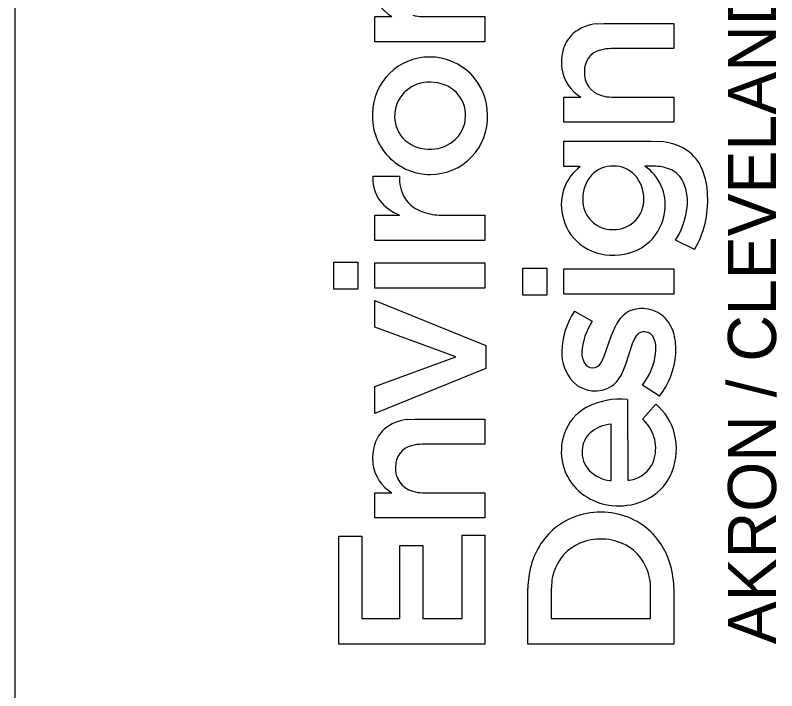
# Model space of a CAD drawing. Extents: x -0.3 to 34, y 0 to 22.
# Drawn here: x 32 to 32.901, y 2.583 to 3.382 of the extents above; entities that cross this region are included whole.
import ezdxf

# ---------------------------------------------------------------- set-up
doc = ezdxf.new("R2010")
doc.units = 0
doc.layers.add('SH_Border', color=7, linetype='Continuous')
doc.layers.add('SH_Data', color=7, linetype='Continuous')

msp = doc.modelspace()

# ---------------------------------------------------------------- linework, layer by layer
at = {"layer": 'SH_Border'}
msp.add_line((32, 0.5), (32, 21.5), dxfattribs=at)
at = {"layer": 'SH_Data'}
for p, q in [((32.42542, 3.38066), (32.44552, 3.38071)), ((32.42542, 3.35086), (32.42542, 3.38066)), ((32.48222, 3.38071), (32.55569, 3.38071)), ((32.55569, 3.38071), (32.55571, 3.35096)), ((32.68784, 3.3722), (32.69634, 3.37266)), ((32.69634, 3.37266), (32.77916, 3.37266)), ((32.77916, 3.37266), (32.77917, 3.34287)), ((32.55571, 3.35096), (32.42542, 3.35086)), ((32.77917, 3.34287), (32.70485, 3.3428)), ((32.64888, 3.2855), (32.66897, 3.28555)), ((32.64888, 3.25569), (32.64888, 3.2855)), ((32.70568, 3.28555), (32.77915, 3.28555)), ((32.77915, 3.28555), (32.77917, 3.25579)), ((32.77917, 3.25579), (32.64888, 3.25569)), ((32.6489, 3.20336), (32.64889, 3.23322)), ((32.64889, 3.23322), (32.75236, 3.23322)), ((32.75236, 3.23322), (32.76191, 3.23285)), ((32.66836, 3.20336), (32.6489, 3.20336)), ((32.75763, 3.20356), (32.74487, 3.20361)), ((32.42299, 3.19193), (32.45454, 3.19193)), ((32.42542, 3.14577), (32.45473, 3.14579)), ((32.42542, 3.11593), (32.42542, 3.14577)), ((32.50413, 3.14581), (32.55571, 3.14573)), ((32.55571, 3.14573), (32.55565, 3.11593)), ((32.55565, 3.11593), (32.42542, 3.11593)), ((32.8036, 3.10491), (32.7812, 3.11598)), ((32.37705, 3.05818), (32.37705, 3.09026)), ((32.37705, 3.09026), (32.40543, 3.09026)), ((32.40543, 3.09026), (32.40543, 3.05818)), ((32.42542, 3.05942), (32.42542, 3.08928)), ((32.42542, 3.08928), (32.55571, 3.08928)), ((32.55571, 3.08928), (32.55571, 3.05942)), ((32.60051, 3.05111), (32.60051, 3.08319)), ((32.60051, 3.08319), (32.62889, 3.08319)), ((32.62889, 3.08319), (32.62889, 3.05111)), ((32.64888, 3.05234), (32.64888, 3.0822)), ((32.64888, 3.0822), (32.77917, 3.0822)), ((32.77917, 3.0822), (32.77917, 3.05234)), ((32.40543, 3.05818), (32.37705, 3.05818)), ((32.55571, 3.05942), (32.42542, 3.05942)), ((32.62889, 3.05111), (32.60051, 3.05111)), ((32.77917, 3.05234), (32.64888, 3.05234)), ((32.42542, 3.01327), (32.42542, 3.0446)), ((32.42542, 3.0446), (32.5567, 2.9913)), ((32.66151, 3.03207), (32.68268, 3.02025)), ((32.52117, 2.97798), (32.42542, 3.01327)), ((32.70483, 3.00258), (32.71036, 3.01526)), ((32.69675, 2.97868), (32.70483, 3.00258)), ((32.73342, 3.00101), (32.72985, 2.9933)), ((32.5567, 2.9913), (32.5567, 2.96441)), ((32.72985, 2.9933), (32.72213, 2.96882)), ((32.42542, 2.94294), (32.52117, 2.97798)), ((32.69299, 2.97117), (32.69675, 2.97868)), ((32.5567, 2.96441), (32.42542, 2.91086)), ((32.72213, 2.96882), (32.71822, 2.95921)), ((32.42542, 2.91086), (32.42542, 2.94294)), ((32.76214, 2.93141), (32.74198, 2.94469)), ((32.72453, 2.92747), (32.72463, 2.83195)), ((32.74228, 2.90465), (32.75768, 2.922)), ((32.46439, 2.90397), (32.47289, 2.90443)), ((32.47289, 2.90443), (32.55571, 2.90443)), ((32.55571, 2.90443), (32.55571, 2.87465)), ((32.70489, 2.83182), (32.70489, 2.89834)), ((32.55571, 2.87465), (32.4814, 2.87457)), ((32.70361, 2.83165), (32.70489, 2.83182)), ((32.42542, 2.81728), (32.44552, 2.81733)), ((32.42542, 2.78747), (32.42542, 2.81728)), ((32.48222, 2.81733), (32.55569, 2.81733)), ((32.55569, 2.81733), (32.55571, 2.78756)), ((32.55571, 2.78756), (32.42542, 2.78747)), ((32.38298, 2.63791), (32.38298, 2.76598)), ((32.38298, 2.76598), (32.41012, 2.76598)), ((32.41012, 2.76598), (32.41012, 2.66827)), ((32.52857, 2.66827), (32.52857, 2.76722)), ((32.52857, 2.76722), (32.55571, 2.76722)), ((32.55571, 2.76722), (32.55571, 2.63791)), ((32.45503, 2.66827), (32.45503, 2.75488)), ((32.45503, 2.75488), (32.48218, 2.75488)), ((32.48218, 2.75488), (32.48218, 2.66827)), ((32.77847, 2.71497), (32.77917, 2.7021)), ((32.60643, 2.63799), (32.60644, 2.704)), ((32.63465, 2.71178), (32.63407, 2.7023)), ((32.63407, 2.7023), (32.63407, 2.66838)), ((32.75149, 2.66834), (32.75153, 2.70239)), ((32.77917, 2.7021), (32.77917, 2.638)), ((32.41012, 2.66827), (32.45503, 2.66827)), ((32.48218, 2.66827), (32.52857, 2.66827)), ((32.63407, 2.66838), (32.75149, 2.66834)), ((32.55571, 2.63791), (32.38298, 2.63791)), ((32.77917, 2.638), (32.60643, 2.63799))]:
    msp.add_line(p, q, dxfattribs=at)
for points in [[(32.42542, 3.35086), (32.42542, 3.38066), (32.44552, 3.38071)], [(32.48222, 3.38071), (32.55569, 3.38071), (32.55571, 3.35096), (32.42542, 3.35086)], [(32.68784, 3.3722), (32.69634, 3.37266), (32.77916, 3.37266), (32.77917, 3.34287), (32.70485, 3.3428)], [(32.64888, 3.25569), (32.64888, 3.2855), (32.66897, 3.28555)], [(32.70568, 3.28555), (32.77915, 3.28555), (32.77917, 3.25579), (32.64888, 3.25569)], [(32.66836, 3.20336), (32.6489, 3.20336), (32.64889, 3.23322), (32.75236, 3.23322), (32.76191, 3.23285)], [(32.75763, 3.20356), (32.74487, 3.20361)], [(32.42299, 3.19193), (32.45454, 3.19193)], [(32.50413, 3.14581), (32.55571, 3.14573), (32.55565, 3.11593), (32.42542, 3.11593)], [(32.42542, 3.11593), (32.42542, 3.14577), (32.45473, 3.14579)], [(32.8036, 3.10491), (32.7812, 3.11598)], [(32.66151, 3.03207), (32.68268, 3.02025)], [(32.69299, 2.97117), (32.69675, 2.97868), (32.70483, 3.00258), (32.71036, 3.01526)], [(32.73342, 3.00101), (32.72985, 2.9933), (32.72213, 2.96882), (32.71822, 2.95921)], [(32.76214, 2.93141), (32.74198, 2.94469)], [(32.72453, 2.92747), (32.72463, 2.83195)], [(32.74228, 2.90465), (32.75768, 2.922)], [(32.46439, 2.90397), (32.47289, 2.90443), (32.55571, 2.90443), (32.55571, 2.87465), (32.4814, 2.87457)], [(32.70361, 2.83165), (32.70489, 2.83182), (32.70489, 2.89834)], [(32.42542, 2.78747), (32.42542, 2.81728), (32.44552, 2.81733)], [(32.48222, 2.81733), (32.55569, 2.81733), (32.55571, 2.78756), (32.42542, 2.78747)], [(32.77847, 2.71497), (32.77917, 2.7021), (32.77917, 2.638), (32.60643, 2.63799)], [(32.60643, 2.63799), (32.60644, 2.704)], [(32.63465, 2.71178), (32.63407, 2.7023), (32.63407, 2.66838), (32.75149, 2.66834), (32.75153, 2.70239)]]:
    msp.add_lwpolyline(points, dxfattribs=at)
for points in [[(32.37705, 3.05818), (32.37705, 3.09026), (32.40543, 3.09026), (32.40543, 3.05818)], [(32.42542, 3.05942), (32.42542, 3.08928), (32.55571, 3.08928), (32.55571, 3.05942)], [(32.60051, 3.05111), (32.60051, 3.08319), (32.62889, 3.08319), (32.62889, 3.05111)], [(32.64888, 3.05234), (32.64888, 3.0822), (32.77917, 3.0822), (32.77917, 3.05234)], [(32.42542, 2.91086), (32.42542, 2.94294), (32.52117, 2.97798), (32.42542, 3.01327), (32.42542, 3.0446), (32.5567, 2.9913), (32.5567, 2.96441)], [(32.38298, 2.63791), (32.38298, 2.76598), (32.41012, 2.76598), (32.41012, 2.66827), (32.45503, 2.66827), (32.45503, 2.75488), (32.48218, 2.75488), (32.48218, 2.66827), (32.52857, 2.66827), (32.52857, 2.76722), (32.55571, 2.76722), (32.55571, 2.63791)]]:
    msp.add_lwpolyline(points, close=True, dxfattribs=at)
for centre, radius, start, end in [((32.47027, 3.42141), 0.04763, 188.96462, 238.69865), ((32.47027, 3.42141), 0.04763, 188.96462, 238.69865), ((32.48183, 3.42286), 0.04215, 254.08913, 270.52838), ((32.48183, 3.42286), 0.04215, 254.08913, 270.52838), ((32.69216, 3.32251), 0.04988, 94.97056, 130.22484), ((32.69216, 3.32251), 0.04988, 94.97056, 130.22484), ((32.68694, 3.33085), 0.04016, 132.22383, 161.68229), ((32.68694, 3.33085), 0.04016, 132.22383, 161.68229), ((32.70217, 3.32642), 0.05602, 162.27398, 187.79173), ((32.70217, 3.32642), 0.05602, 162.27398, 187.79173), ((32.70453, 3.29679), 0.04601, 89.60515, 105.33026), ((32.70453, 3.29679), 0.04601, 89.60515, 105.33026), ((32.69828, 3.31689), 0.02498, 103.68683, 182.21395), ((32.69828, 3.31689), 0.02498, 103.68683, 182.21395), ((32.49014, 3.26543), 0.0674, 89.84756, 179.64047), ((32.49014, 3.26543), 0.0674, 89.84756, 179.64047), ((32.49057, 3.26474), 0.0681, 359.54009, 90.21138), ((32.49057, 3.26474), 0.0681, 359.54009, 90.21138), ((32.69372, 3.32624), 0.04763, 188.96462, 238.69865), ((32.69372, 3.32624), 0.04763, 188.96462, 238.69865), ((32.7008, 3.31381), 0.02757, 175.58441, 255.13816), ((32.7008, 3.31381), 0.02757, 175.58441, 255.13816), ((32.48923, 3.26263), 0.0404, 87.04809, 175.57259), ((32.48923, 3.26263), 0.0404, 87.04809, 175.57259), ((32.49204, 3.25999), 0.04299, 45.84264, 90.98008), ((32.49204, 3.25999), 0.04299, 45.84264, 90.98008), ((32.49458, 3.26421), 0.03821, 357.88569, 44.15902), ((32.49458, 3.26421), 0.03821, 357.88569, 44.15902), ((32.70529, 3.32769), 0.04215, 254.08913, 270.52838), ((32.70529, 3.32769), 0.04215, 254.08913, 270.52838), ((32.49083, 3.26209), 0.06819, 176.8344, 270.40384), ((32.49083, 3.26209), 0.06819, 176.8344, 270.40384), ((32.48729, 3.2625), 0.03848, 175.15378, 221.14706), ((32.48729, 3.2625), 0.03848, 175.15378, 221.14706), ((32.49123, 3.26139), 0.06749, 270.06243, 2.37759), ((32.49123, 3.26139), 0.06749, 270.06243, 2.37759), ((32.49446, 3.26318), 0.0383, 308.28936, 359.43468), ((32.49446, 3.26318), 0.0383, 308.28936, 359.43468), ((32.48919, 3.26607), 0.04228, 223.09994, 268.80895), ((32.48919, 3.26607), 0.04228, 223.09994, 268.80895), ((32.49096, 3.2679), 0.04418, 266.56515, 308.06078), ((32.49096, 3.2679), 0.04418, 266.56515, 308.06078), ((32.75907, 3.16789), 0.06503, 53.40344, 87.49062), ((32.75907, 3.16789), 0.06503, 53.40344, 87.49062), ((32.76517, 3.18039), 0.05141, 21.60748, 50.5577), ((32.76517, 3.18039), 0.05141, 21.60748, 50.5577), ((32.70292, 3.15813), 0.05692, 127.37482, 192.22468), ((32.70292, 3.15813), 0.05692, 127.37482, 192.22468), ((32.70693, 3.16927), 0.0346, 88.47302, 136.42562), ((32.70693, 3.16927), 0.0346, 88.47302, 136.42562), ((32.70814, 3.16963), 0.03424, 44.27195, 90.47623), ((32.70814, 3.16963), 0.03424, 44.27195, 90.47623), ((32.71421, 3.15829), 0.05472, 352.1125, 55.92295), ((32.71421, 3.15829), 0.05472, 352.1125, 55.92295), ((32.75666, 3.15725), 0.04633, 65.01687, 88.8011), ((32.75666, 3.15725), 0.04633, 65.01687, 88.8011), ((32.7626, 3.17155), 0.03085, 26.26808, 63.80301), ((32.7626, 3.17155), 0.03085, 26.26808, 63.80301), ((32.73069, 3.16714), 0.08835, 1.15143, 21.3627), ((32.73069, 3.16714), 0.08835, 1.15143, 21.3627), ((32.46616, 3.18882), 0.04329, 175.87313, 216.34747), ((32.46616, 3.18882), 0.04329, 175.87313, 216.34747), ((32.50087, 3.18948), 0.04639, 176.9688, 209.60636), ((32.50087, 3.18948), 0.04639, 176.9688, 209.60636), ((32.71141, 3.16602), 0.0401, 137.46739, 182.33237), ((32.71141, 3.16602), 0.0401, 137.46739, 182.33237), ((32.70368, 3.166), 0.03996, 358.57141, 43.53765), ((32.70368, 3.166), 0.03996, 358.57141, 43.53765), ((32.73565, 3.16154), 0.05953, 349.30734, 23.43071), ((32.73565, 3.16154), 0.05953, 349.30734, 23.43071), ((32.47466, 3.19716), 0.05511, 218.09809, 248.7907), ((32.47466, 3.19716), 0.05511, 218.09809, 248.7907), ((32.49514, 3.18814), 0.04079, 211.94466, 253.2028), ((32.49514, 3.18814), 0.04079, 211.94466, 253.2028), ((32.70645, 3.1637), 0.03511, 178.88208, 271.08374), ((32.70645, 3.1637), 0.03511, 178.88208, 271.08374), ((32.70818, 3.16404), 0.03546, 268.27882, 1.55016), ((32.70818, 3.16404), 0.03546, 268.27882, 1.55016), ((32.70538, 3.16244), 0.11383, 329.6388, 3.25998), ((32.70538, 3.16244), 0.11383, 329.6388, 3.25998), ((32.50465, 3.2165), 0.07069, 252.46555, 269.57296), ((32.50465, 3.2165), 0.07069, 252.46555, 269.57296), ((32.70463, 3.15696), 0.05837, 190.75182, 231.28919), ((32.70463, 3.15696), 0.05837, 190.75182, 231.28919), ((32.70988, 3.15708), 0.05887, 313.74196, 353.8554), ((32.70988, 3.15708), 0.05887, 313.74196, 353.8554), ((32.70738, 3.16334), 0.08771, 327.31495, 351.57478), ((32.70738, 3.16334), 0.08771, 327.31495, 351.57478), ((32.70632, 3.16112), 0.06269, 232.46061, 272.59022), ((32.70632, 3.16112), 0.06269, 232.46061, 272.59022), ((32.70954, 3.15901), 0.06051, 269.6361, 312.70877), ((32.70954, 3.15901), 0.06051, 269.6361, 312.70877), ((32.73636, 2.98258), 0.08973, 146.53104, 178.7571), ((32.73636, 2.98258), 0.08973, 146.53104, 178.7571), ((32.74661, 2.99713), 0.04053, 125.51182, 153.41595), ((32.74661, 2.99713), 0.04053, 125.51182, 153.41595), ((32.7406, 3.0026), 0.03263, 80.17192, 122.51969), ((32.7406, 3.0026), 0.03263, 80.17192, 122.51969), ((32.74278, 2.99824), 0.03667, 47.79344, 84.68918), ((32.74278, 2.99824), 0.03667, 47.79344, 84.68918), ((32.74519, 2.9789), 0.07495, 146.51121, 176.91007), ((32.74519, 2.9789), 0.07495, 146.51121, 176.91007), ((32.73788, 2.9946), 0.04267, 14.9966, 46.20632), ((32.73788, 2.9946), 0.04267, 14.9966, 46.20632), ((32.74384, 2.99631), 0.01143, 76.66094, 155.7053), ((32.74384, 2.99631), 0.01143, 76.66094, 155.7053), ((32.74397, 2.99511), 0.01256, 21.5098, 78.52618), ((32.74397, 2.99511), 0.01256, 21.5098, 78.52618), ((32.71044, 2.98674), 0.07121, 355.83062, 15.39138), ((32.71044, 2.98674), 0.07121, 355.83062, 15.39138), ((32.72592, 2.98766), 0.03209, 354.57264, 22.06805), ((32.72592, 2.98766), 0.03209, 354.57264, 22.06805), ((32.69666, 2.98238), 0.05005, 177.53659, 222.79318), ((32.69666, 2.98238), 0.05005, 177.53659, 222.79318), ((32.6931, 2.98233), 0.02276, 178.47474, 211.08679), ((32.6931, 2.98233), 0.02276, 178.47474, 211.08679), ((32.68248, 2.99149), 0.0757, 321.81101, 354.79685), ((32.68248, 2.99149), 0.0757, 321.81101, 354.79685), ((32.68952, 2.9882), 0.09219, 321.9777, 355.87384), ((32.68952, 2.9882), 0.09219, 321.9777, 355.87384), ((32.68331, 2.9767), 0.01148, 212.23676, 268.37769), ((32.68331, 2.9767), 0.01148, 212.23676, 268.37769), ((32.68342, 2.97589), 0.01067, 267.71603, 333.73375), ((32.68342, 2.97589), 0.01067, 267.71603, 333.73375), ((32.68098, 2.9758), 0.04077, 308.08772, 335.98736), ((32.68098, 2.9758), 0.04077, 308.08772, 335.98736), ((32.68599, 2.97535), 0.0375, 225.98539, 302.47965), ((32.68599, 2.97535), 0.0375, 225.98539, 302.47965), ((32.7152, 2.84414), 0.08384, 83.61499, 118.28755), ((32.7152, 2.84414), 0.08384, 83.61499, 118.28755), ((32.71744, 2.87167), 0.06443, 13.53365, 51.36148), ((32.71744, 2.87167), 0.06443, 13.53365, 51.36148), ((32.70239, 2.86906), 0.05583, 118.83082, 160.62438), ((32.70239, 2.86906), 0.05583, 118.83082, 160.62438), ((32.46871, 2.85428), 0.04988, 94.96958, 130.22249), ((32.46871, 2.85428), 0.04988, 94.96958, 130.22249), ((32.70378, 2.86556), 0.05486, 19.03571, 45.44059), ((32.70378, 2.86556), 0.05486, 19.03571, 45.44059), ((32.46348, 2.86263), 0.04015, 132.22192, 161.68183), ((32.46348, 2.86263), 0.04015, 132.22192, 161.68183), ((32.70785, 2.85609), 0.04235, 94.00805, 130.88169), ((32.70785, 2.85609), 0.04235, 94.00805, 130.88169), ((32.71041, 2.86612), 0.06437, 160.52012, 215.78311), ((32.71041, 2.86612), 0.06437, 160.52012, 215.78311), ((32.70048, 2.86628), 0.02985, 132.98507, 177.179), ((32.70048, 2.86628), 0.02985, 132.98507, 177.179), ((32.71069, 2.8697), 0.047, 344.60586, 17.007), ((32.71069, 2.8697), 0.047, 344.60586, 17.007), ((32.70635, 2.86921), 0.07579, 339.3542, 13.37853), ((32.70635, 2.86921), 0.07579, 339.3542, 13.37853), ((32.47872, 2.85819), 0.05601, 162.27355, 187.79185), ((32.47872, 2.85819), 0.05601, 162.27355, 187.79185), ((32.48108, 2.82856), 0.04601, 89.60494, 105.3284), ((32.48108, 2.82856), 0.04601, 89.60494, 105.3284), ((32.47482, 2.84867), 0.02498, 103.68646, 182.21874), ((32.47482, 2.84867), 0.02498, 103.68646, 182.21874), ((32.7017, 2.86503), 0.03115, 175.00126, 223.28301), ((32.7017, 2.86503), 0.03115, 175.00126, 223.28301), ((32.7224, 2.86715), 0.03504, 288.00773, 343.55078), ((32.7224, 2.86715), 0.03504, 288.00773, 343.55078), ((32.47026, 2.85802), 0.04762, 188.96199, 238.70369), ((32.47026, 2.85802), 0.04762, 188.96199, 238.70369), ((32.47735, 2.84558), 0.02756, 175.58538, 255.14386), ((32.47735, 2.84558), 0.02756, 175.58538, 255.14386), ((32.70891, 2.87363), 0.04231, 225.06188, 262.79738), ((32.70891, 2.87363), 0.04231, 225.06188, 262.79738), ((32.71894, 2.8652), 0.0626, 300.94269, 338.73225), ((32.71894, 2.8652), 0.0626, 300.94269, 338.73225), ((32.72474, 2.85216), 0.02021, 269.7003, 294.8711), ((32.72474, 2.85216), 0.02021, 269.7003, 294.8711), ((32.71253, 2.87054), 0.06872, 217.74516, 271.65431), ((32.71253, 2.87054), 0.06872, 217.74516, 271.65431), ((32.48183, 2.85948), 0.04215, 254.09162, 270.52835), ((32.48183, 2.85948), 0.04215, 254.09162, 270.52835), ((32.71549, 2.87241), 0.07056, 269.20477, 300.33412), ((32.71549, 2.87241), 0.07056, 269.20477, 300.33412), ((32.69229, 2.70792), 0.08641, 81.19402, 125.99844), ((32.69229, 2.70792), 0.08641, 81.19402, 125.99844), ((32.69458, 2.71132), 0.08272, 37.85208, 82.40204), ((32.69458, 2.71132), 0.08272, 37.85208, 82.40204), ((32.69387, 2.70893), 0.08654, 127.23621, 165.14796), ((32.69387, 2.70893), 0.08654, 127.23621, 165.14796), ((32.68893, 2.70782), 0.05398, 106.18808, 157.38609), ((32.68893, 2.70782), 0.05398, 106.18808, 157.38609), ((32.69279, 2.69862), 0.06389, 55.67272, 107.20935), ((32.69279, 2.69862), 0.06389, 55.67272, 107.20935), ((32.68586, 2.70567), 0.09308, 5.73329, 37.30396), ((32.68586, 2.70567), 0.09308, 5.73329, 37.30396), ((32.69291, 2.70499), 0.05867, 357.46616, 52.26647), ((32.69291, 2.70499), 0.05867, 357.46616, 52.26647), ((32.71426, 2.70281), 0.10783, 164.7861, 179.37039), ((32.71426, 2.70281), 0.10783, 164.7861, 179.37039), ((32.69829, 2.70389), 0.06412, 157.35705, 172.92755), ((32.69829, 2.70389), 0.06412, 157.35705, 172.92755)]:
    msp.add_arc(centre, radius, start, end, dxfattribs=at)

# ---------------------------------------------------------------- texts
msp.add_text('AKRON / CLEVELAND / COLUMBUS', height=0.056969, rotation=90, dxfattribs=at).set_placement((32.90012, 2.638))

doc.saveas('drawing.dxf')
